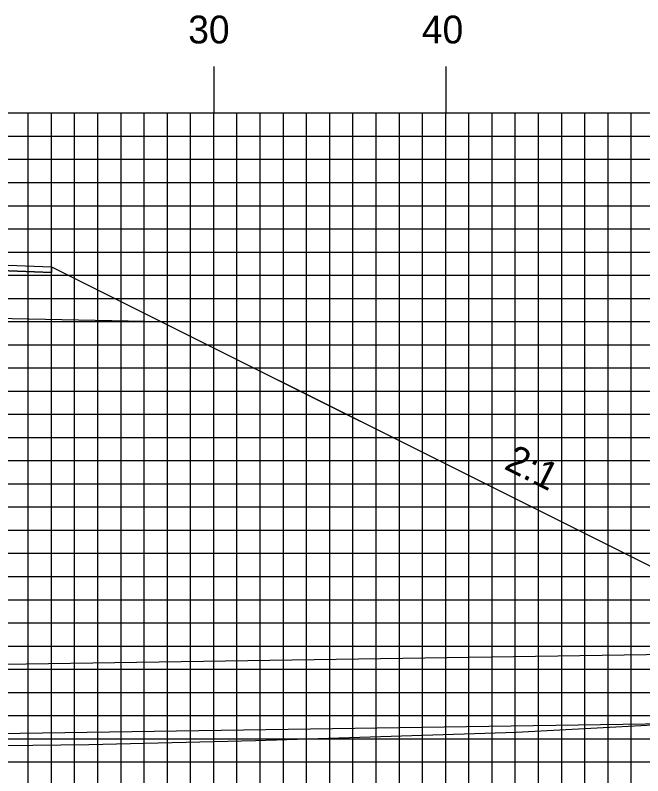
# Model space of a CAD drawing. Extents: x 1789730 to 1790074, y 442591 to 442811.
# Drawn here: x 1789917.62 to 1789944.68, y 442615.07 to 442647.88 of the extents above; entities that cross this region are included whole.
import ezdxf

# ---------------------------------------------------------------- set-up
doc = ezdxf.new("R2010")
doc.units = 0
for name, color, linetype in [('ANNOTATION', 7, 'Continuous'), ('D_Drainage_Culvert', 7, 'Continuous'), ('D_Roadway_Centerline', 7, 'Continuous'), ('D_Roadway_Edge_Shoulder', 7, 'Continuous'), ('D_Roadway_SlopeLines', 7, 'Continuous'), ('D_Roadway_SubGrade', 7, 'Continuous'), ('H_V ANNOTATION', 7, 'Continuous'), ('MAJOR', 7, 'Continuous'), ('MINOR', 7, 'Continuous'), ('S_Roadway_Centerline', 7, 'Continuous')]:
    doc.layers.add(name, color=color, linetype=linetype)

msp = doc.modelspace()

# ---------------------------------------------------------------- linework, layer by layer
at = {"layer": 'D_Drainage_Culvert'}
msp.add_lwpolyline([(1789830.264, 442615.576), (1789830.219, 442618.576), (1789958.204, 442620.494), (1789958.249, 442617.494)], close=True, dxfattribs=at)
at = {"layer": 'D_Roadway_Centerline'}
msp.add_lwpolyline([(1789830.28, 442615.576), (1789868.433, 442634.652), (1789873.183, 442637.027), (1789876.183, 442637.147), (1789884.183, 442637.467), (1789896.183, 442637.707), (1789908.183, 442637.467), (1789916.183, 442637.147), (1789919.183, 442637.027), (1789923.933, 442634.652), (1789958.249, 442617.494)], dxfattribs=at)
at = {"layer": 'D_Roadway_Edge_Shoulder'}
msp.add_lwpolyline([(1789908.183, 442637.467), (1789916.183, 442637.147), (1789916.183, 442637.147), (1789919.183, 442637.027), (1789919.183, 442636.777), (1789908.183, 442637.217)], close=True, dxfattribs=at)
at = {"layer": 'D_Roadway_SlopeLines'}
msp.add_lwpolyline([(1789919.183, 442637.027), (1789958.249, 442617.494)], dxfattribs=at)
at = {"layer": 'D_Roadway_SubGrade'}
msp.add_lwpolyline([(1789908.183, 442636.801), (1789908.183, 442637.217), (1789919.183, 442636.777), (1789919.183, 442637.027), (1789923.933, 442634.652), (1789908.183, 442634.967)], close=True, dxfattribs=at)
at = {"layer": 'MAJOR'}
for p, q in [((1789926.183, 442645.669), (1789926.183, 442643.665)), ((1789936.183, 442645.669), (1789936.183, 442643.665)), ((1789756.183, 442643.665), (1790036.183, 442643.665)), ((1789756.183, 442643.665), (1790036.183, 442643.665)), ((1789926.183, 442608.665), (1789926.183, 442643.665)), ((1789936.183, 442608.665), (1789936.183, 442643.665)), ((1789756.183, 442638.665), (1790036.183, 442638.665)), ((1789756.183, 442633.665), (1790036.183, 442633.665)), ((1789756.183, 442628.665), (1790036.183, 442628.665)), ((1789756.183, 442623.665), (1790036.183, 442623.665)), ((1789756.183, 442618.665), (1790036.183, 442618.665))]:
    msp.add_line(p, q, dxfattribs=at)
at = {"layer": 'MINOR'}
for p, q in [((1789918.183, 442608.665), (1789918.183, 442643.665)), ((1789919.183, 442608.665), (1789919.183, 442643.665)), ((1789920.183, 442608.665), (1789920.183, 442643.665)), ((1789921.183, 442608.665), (1789921.183, 442643.665)), ((1789922.183, 442608.665), (1789922.183, 442643.665)), ((1789923.183, 442608.665), (1789923.183, 442643.665)), ((1789924.183, 442608.665), (1789924.183, 442643.665)), ((1789925.183, 442608.665), (1789925.183, 442643.665)), ((1789927.183, 442608.665), (1789927.183, 442643.665)), ((1789928.183, 442608.665), (1789928.183, 442643.665)), ((1789929.183, 442608.665), (1789929.183, 442643.665)), ((1789930.183, 442608.665), (1789930.183, 442643.665)), ((1789931.183, 442608.665), (1789931.183, 442643.665)), ((1789932.183, 442608.665), (1789932.183, 442643.665)), ((1789933.183, 442608.665), (1789933.183, 442643.665)), ((1789934.183, 442608.665), (1789934.183, 442643.665)), ((1789935.183, 442608.665), (1789935.183, 442643.665)), ((1789937.183, 442608.665), (1789937.183, 442643.665)), ((1789938.183, 442608.665), (1789938.183, 442643.665)), ((1789939.183, 442608.665), (1789939.183, 442643.665)), ((1789940.183, 442608.665), (1789940.183, 442643.665)), ((1789941.183, 442608.665), (1789941.183, 442643.665)), ((1789942.183, 442608.665), (1789942.183, 442643.665)), ((1789943.183, 442608.665), (1789943.183, 442643.665)), ((1789944.183, 442608.665), (1789944.183, 442643.665)), ((1789756.183, 442642.665), (1790036.183, 442642.665)), ((1789756.183, 442641.665), (1790036.183, 442641.665)), ((1789756.183, 442640.665), (1790036.183, 442640.665)), ((1789756.183, 442639.665), (1790036.183, 442639.665)), ((1789756.183, 442637.665), (1790036.183, 442637.665)), ((1789756.183, 442636.665), (1790036.183, 442636.665)), ((1789756.183, 442635.665), (1790036.183, 442635.665)), ((1789756.183, 442634.665), (1790036.183, 442634.665)), ((1789756.183, 442632.665), (1790036.183, 442632.665)), ((1789756.183, 442631.665), (1790036.183, 442631.665)), ((1789756.183, 442630.665), (1790036.183, 442630.665)), ((1789756.183, 442629.665), (1790036.183, 442629.665)), ((1789756.183, 442627.665), (1790036.183, 442627.665)), ((1789756.183, 442626.665), (1790036.183, 442626.665)), ((1789756.183, 442625.665), (1790036.183, 442625.665)), ((1789756.183, 442624.665), (1790036.183, 442624.665)), ((1789756.183, 442622.665), (1790036.183, 442622.665)), ((1789756.183, 442621.665), (1790036.183, 442621.665)), ((1789756.183, 442620.665), (1790036.183, 442620.665)), ((1789756.183, 442619.665), (1790036.183, 442619.665)), ((1789756.183, 442617.665), (1790036.183, 442617.665)), ((1789756.183, 442616.665), (1790036.183, 442616.665)), ((1789756.183, 442615.665), (1790036.183, 442615.665))]:
    msp.add_line(p, q, dxfattribs=at)
at = {"layer": 'S_Roadway_Centerline'}
msp.add_lwpolyline([(1789866.101, 442615.468), (1789877.117, 442615.721), (1789884.245, 442615.898), (1789891.899, 442616.022), (1789902.339, 442616.224), (1789913.548, 442616.33), (1789920.798, 442616.417), (1789927.986, 442616.59), (1789939.227, 442616.951), (1789948.345, 442617.441), (1789967.66, 442617.545), (1789973.155, 442617.663), (1789975.475, 442617.594), (1789981.871, 442617.693), (1789993.214, 442617.848), (1789995.716, 442617.911), (1790007.509, 442618.287), (1790012.574, 442618.507), (1790017.23, 442618.665), (1790030.7, 442619.441), (1790036.183, 442619.425)], dxfattribs=at)

# ---------------------------------------------------------------- texts
at = {"layer": 'ANNOTATION'}
msp.add_text('2:1', height=1.2, rotation=333.4349, dxfattribs=at).set_placement((1789938.65, 442628.33))
at = {"layer": 'H_V ANNOTATION'}
for s, p in [('30', (1789925.08, 442646.665)), ('40', (1789935.155, 442646.665))]:
    msp.add_text(s, height=1.2, dxfattribs=at).set_placement(p)

doc.saveas('drawing.dxf')
